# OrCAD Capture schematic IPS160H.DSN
size C
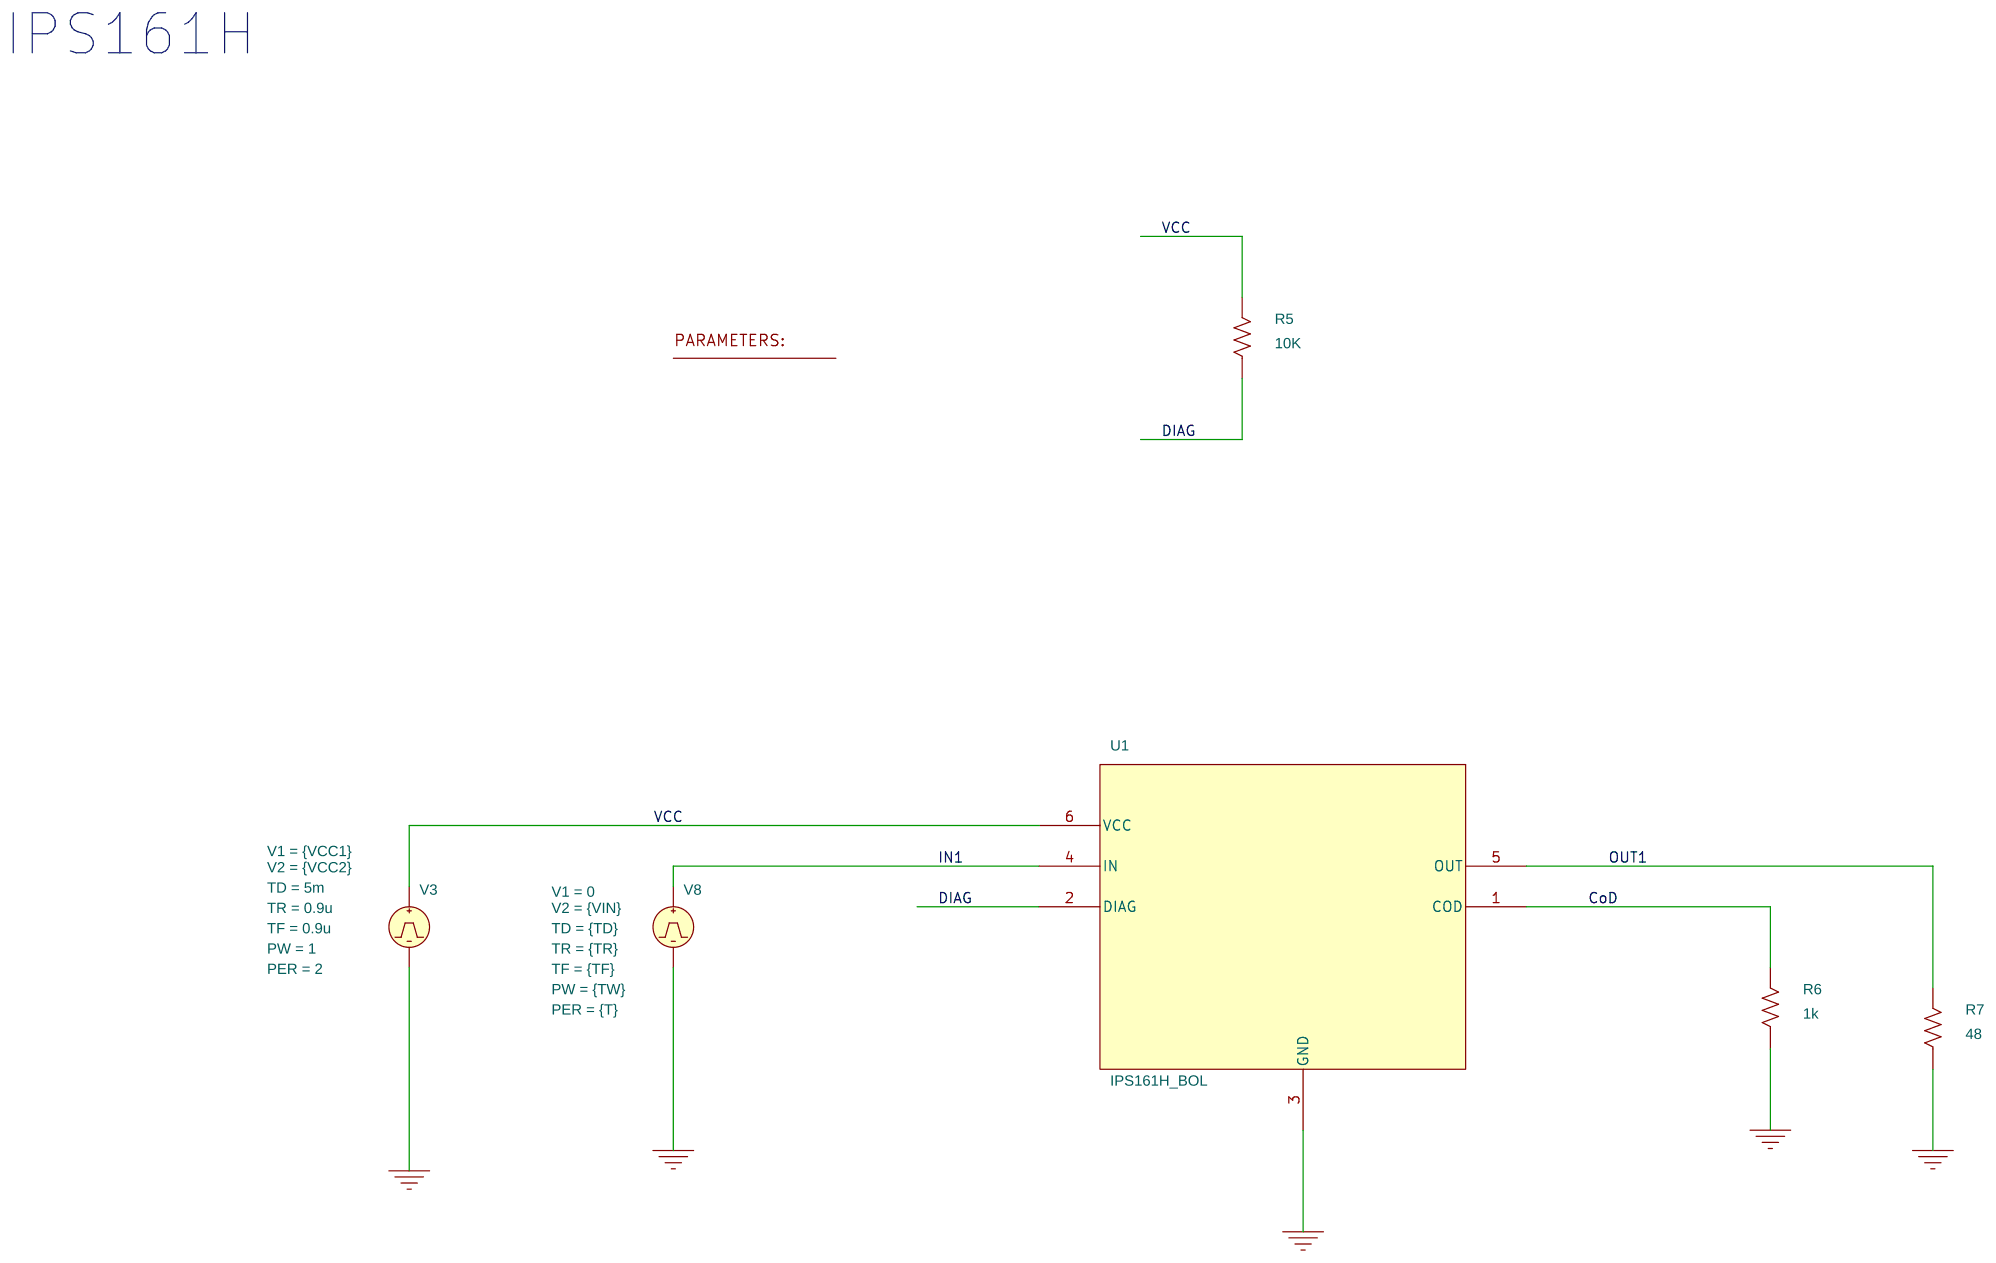
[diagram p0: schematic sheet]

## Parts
1  PARAM
R5  10K  [AX/RC05]
R6  1k  [AX/RC05]
R7  48  [AX/RC05]
U1  IPS161H_BOL
V3  VPULSE
V8  VPULSE

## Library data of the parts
1 = PARAM: T: 200m; TD: 5m; TD2: 10m; TF: 0.09u; TR: 0.09u; TW: {0.8*T}; VCC1: 0; VCC2: 24; VIN: 3.3
R5-R7 = R
U1 = IPS161H_BOL
V3 = VPULSE: PER: 2; PW: 1; TD: 5m; TF: 0.9u; TR: 0.9u; V1: {VCC1}; V2: {VCC2}
V8 = VPULSE: PER: {T}; PW: {TW}; TD: {TD}; TF: {TF}; TR: {TR}; V1: 0; V2: {VIN}

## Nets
VCC: R5.2 U1.6(VCC) V3.1(+)
0: R6.1 R7.1 U1.3(GND) V3.2(-) V8.2(-)
CoD: R6.2 U1.1(COD)
DIAG: R5.1 U1.2(DIAG)
IN1: U1.4(IN) V8.1(+)
OUT1: R7.2 U1.5(OUT)

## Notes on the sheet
- IPS161H
